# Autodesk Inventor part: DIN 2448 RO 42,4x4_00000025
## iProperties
Created: 2006-02
Part Number: DIN 2448 RO 42,4x4_00000025
Material: Default
Document SubType Name: Modeling
Designer: FranzK
Stock Number: DIN 2448 RO 42,4x4
Mass: 421.966 g
Surface Area: 2123.47 cm^2
Volume: 421.966 cm^3
Density: 1 g/cm^3
G_L: 890.000 mm
G_W: 42.400 mm
G_H: 42.400 mm
AFG_Item: 42.4 x 4
CSToolsMass: 0.4
CSToolsVolume: 421966.0
CSToolsArea: 2123.0
Author: FranzK
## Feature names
1. AFG_Detailed_DIN 2448 RO 42,4x4_00000025 [Extrusion]
2. AFG_Simplified_DIN 2448 RO 42,4x4_00000025 [Extrusion]
3. AFG_StartExtrusion_1 [Extrusion]
4. AFG_StartExtrusion_2 [Extrusion]
